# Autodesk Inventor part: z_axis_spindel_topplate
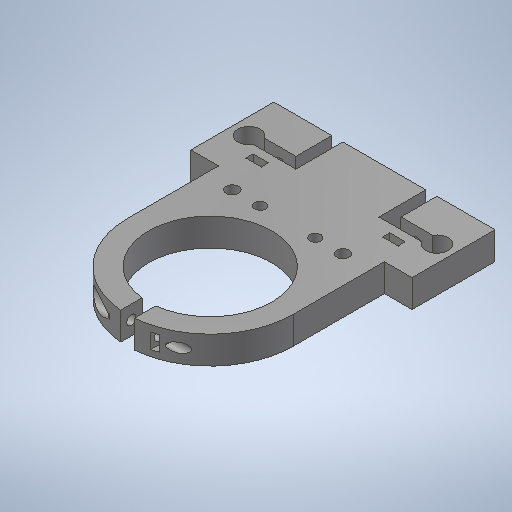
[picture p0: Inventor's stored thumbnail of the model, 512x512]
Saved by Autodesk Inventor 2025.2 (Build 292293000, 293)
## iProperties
Created: 2025-04
Part Number: z_axis_spindel_topplate
Material: 1.0037 S235JR
Document SubType Name: Modeling
Designer: BennF
Density: 7.85 g/cm^3
Appearance: Stahl
Author: BennF
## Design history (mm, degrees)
sketch "Sketch2"
  geometry: L1 (-2.5, -29.896)-(-2.5, -22.159); L2 (2.5, -29.896)-(2.5, -22.159); L3 (-30, 0)-(-30, 33); L4 (-40, 63)-(40, 63); L5 (30, 33)-(30, 0); L6 (-30, 33)-(-40, 33); L7 (-40, 33)-(-40, 63); L8 (30, 33)-(40, 33); L9 (40, 33)-(40, 63); A1 r 22.3 centre (0, 0) between (2.5, -22.159) and (-2.5, -22.159); A2 r 30 centre (0, 0) between (-30, 0) and (-2.5, -29.896); A3 r 30 centre (0, 0) between (2.5, -29.896) and (30, 0); 3 further points
  constraints: 18 end point, 7 point on circle, 4 perpendicular, 3 centre point, 3 coincident, 3 vertical, 2 horizontal, 2 horizontal alignment, 2 parallel, 1 midpoint, 1 tangent, 1 vertical alignment
  dimensions: "d0" = 5 distance between parallel lines of L2 L1; "d1" = 22.3 radius of A1; "d63" = 60 distance between parallel lines of L5 L3; "d64" = 80 distance of L4.start L4.end; "d65" = 30 distance of L8.end L4.end; "d83" = 63 distance from line of point (0, 0) L4
extrude "Extrusion1" new body sketch "Sketch2" distance "d4" = 10; taper "d5" = 0 deg
sketch "Sketch3"
  geometry: L1 (-10, 29.896)-(-10, 0) reference; L2 (-10, 0)-(0, 7.736); L3 (0, 29.896)-(0, 0) reference; L4 (0, 0)-(-10, 7.736); L5 (-10, 7.736)-(0, 7.736) reference; L6 (0, 7.736)-(0, 0) reference; L7 (0, 0)-(-10, 0) reference; L8 (-10, 0)-(-10, 7.736) reference; L9 (-10, 92.896)-(0, 92.896) reference; L10 (0, 92.896)-(0, 52.055) reference; L11 (0, 52.055)-(-10, 52.055) reference; L12 (-10, 52.055)-(-10, 92.896) reference; 2 further points
  constraints: 4 end point, 1 coincident, 1 midpoint
hole "Hole1" sketch "Sketch3" at (-5, 3.868) diameter "d6" = 3.4; stored, may be unused: countersink angle "d10" = 90 deg, drill point angle "d12" = 0 deg; dims "d7" = 3, "d8" = 6.5, "d9" = 3.4, "d11" = 3
sketch "Sketch4"
  geometry: L1 (10, 0)-(0, 0) reference; L2 (0, 0)-(0, 7.736) reference; L3 (0, 7.736)-(10, 7.736) reference; L4 (10, 7.736)-(10, 0) reference; L5 (0, 92.896)-(10, 92.896) reference; L6 (10, 92.896)-(10, 52.055) reference; L7 (10, 52.055)-(0, 52.055) reference; L8 (0, 52.055)-(0, 92.896) reference; L9 (0, 7.736)-(10, 0); L10 (0, 0)-(0, 29.896) reference; L11 (10, 7.736)-(0, 0); 2 further points
  constraints: 4 end point, 1 coincident, 1 midpoint
hole "Hole2" sketch "Sketch4" at (5, 3.868) diameter "d13" = 3.4 (= d6); stored, may be unused: countersink angle "d17" = 90 deg, drill point angle "d19" = 0 deg; dims "d14" = 6, "d15" = 4, "d16" = 2, "d18" = 8
workplane "Work Plane1"
sketch "Sketch5"
  geometry: L1 (5, 7.044)-(7.75, 5.456); L2 (7.75, 5.456)-(7.75, 2.28); L3 (7.75, 2.28)-(5, 0.693); L4 (5, 0.693)-(2.25, 2.28); L5 (2.25, 2.28)-(2.25, 5.456); L6 (2.25, 5.456)-(5, 7.044); L7 (7.75, 2.28)-(7.75, 0.848); L8 (10, 50.897)-(0, 50.897) reference; L9 (10, 8.895)-(10, 0.848) reference; L10 (10, 0.848)-(0, 0.848) reference; L11 (0, 0.848)-(0, 8.895) reference; L12 (0, 92.896)-(10, 92.896) reference; L13 (10, 92.896)-(10, 50.897) reference; L14 (0, 8.895)-(10, 8.895) reference; L15 (0, 50.897)-(0, 92.896) reference; L16 (2.25, 2.28)-(2.25, 0.848); C1 r 1.7 at (5, 3.868) reference; 3 further points
  constraints: 16 end point, 2 point on line, 1 coincident, 1 perpendicular, 1 vertical, 1 vertical alignment, 13 other
  dimensions: "d21" = 5.5 distance between parallel lines of L5 L2
extrude "Extrusion2" cut sketch "Sketch5" distance "d22" = 2.5; taper "d23" = 0 deg
sketch "Sketch6"
  geometry: L1 (10, -23.2)-(50, -23.2); 8 further points; 1 other entity
  constraints: 2 end point, 1 coincident, 1 horizontal, 1 horizontal alignment, 1 midpoint, 1 vertical alignment, 2 other
  dimensions: "d52" = 35 dimension on L1; "d53" = 40 distance of L1.start L1.end
hole "Hole3" sketch "Sketch6" at (10, -23.2), (50, -23.2) diameter "d24" = 4.5; stored, may be unused: countersink angle "d28" = 90 deg, drill point angle "d30" = 118 deg; dims "d25" = 8, "d26" = 10, "d27" = 2, "d29" = 11.8
sketch "Sketch7"
  geometry: L1 (40, -23.2)-(20, -23.2); C1 r 2.25 at (50, -23.2) reference; 7 further points; 1 other entity
  constraints: 2 end point, 2 horizontal alignment, 1 horizontal, 1 midpoint, 1 vertical alignment, 2 other
  dimensions: "d40" = 20 distance of L1.start L1.end
hole "Hole4" sketch "Sketch7" at (40, -23.2), (20, -23.2) diameter "d33" = 4; stored, may be unused: countersink angle "d37" = 90 deg, drill point angle "d39" = 0 deg; dims "d34" = 10, "d35" = 6.5, "d36" = 3.4, "d38" = 25
sketch "Sketch10"
  geometry: L1 (-34, 48)-(34, 48); L2 (40, 63)-(-40, 63) reference; 2 further points
  constraints: 2 end point, 1 horizontal, 1 horizontal alignment, 1 midpoint, 1 vertical alignment
  dimensions: "d61" = 68 distance of L1.start L1.end; "d62" = 15 distance between parallel lines of L2 L1
hole "Hole5" sketch "Sketch10" at (-34, 48), (34, 48) diameter "d54" = 8.15; stored, may be unused: countersink angle "d58" = 90 deg, drill point angle "d60" = 118 deg; dims "d55" = 6, "d56" = 6.3, "d57" = 2, "d59" = 8
workpoint "Work Point1"
workplane "Work Plane2"
  workaxis "Work Axis2"
sketch "Sketch11"
  geometry: L1 (27.5, -5)-(27.5, -2.05); L2 (27.5, -2.05)-(5, -2.05); L3 (5, -2.05)-(5, -5); L4 (27.5, -5)-(5, -5); L5 (0, -6.7)-(0, -3.3) reference; L6 (27.5, -10)-(27.5, 0) reference; 3 further points
  constraints: 8 end point, 3 point on line, 2 perpendicular, 1 horizontal, 1 vertical, 1 other
  dimensions: "d66" = 5.9 diameter of L2 L4; "d67" = 5 distance between parallel lines of L5 L3
revolve "Revolution1" sketch "Sketch11" stored, may be unused: angle "d68" = 90 deg
sketch "Sketch12"
  geometry: L1 (40, 63)-(-40, 63) reference; L2 (-30.45, 50)-(-19, 50); L3 (-19, 50)-(-19, 63); L4 (-15, 63)-(-15, 46); L5 (-15, 46)-(-30.45, 46); L6 (19, 63)-(19, 50); L7 (19, 50)-(30.45, 50); L8 (15, 63)-(15, 46); L9 (15, 46)-(30.45, 46); L10 (-19, 50)-(-15, 50); L11 (-19, 50)-(-19, 46); L12 (27.525, 40.4)-(21.925, 40.4); L13 (21.925, 40.4)-(21.925, 43); L14 (21.925, 43)-(27.525, 43); L15 (27.525, 43)-(27.525, 40.4); L16 (-21.925, 40.4)-(-27.525, 40.4); L17 (-27.525, 40.4)-(-27.525, 43); L18 (-27.525, 43)-(-21.925, 43); L19 (-21.925, 43)-(-21.925, 40.4); A1 r 4.075 centre (-34, 48) between (-30.45, 50) and (-30.45, 46) reference; A2 r 4.075 centre (34, 48) between (30.45, 50) and (30.45, 46) reference; 6 further points
  constraints: 36 end point, 8 perpendicular, 8 point on line, 5 midpoint, 4 equal length, 4 parallel, 4 point on circle, 4 vertical alignment, 3 horizontal, 3 vertical, 1 horizontal alignment
  dimensions: "d69" = 4 distance between parallel lines of L5 L2; "d70" = 15 distance from line of L3 A1.centre; "d71" = 3 distance from line of point (22.725, 46) L14; "d72" = 5.6 distance of L16.start L16.end; "d73" = 2.6 distance of L16.end L17.end
extrude "Extrusion4" cut sketch "Sketch12" distance "d74" = 10; taper "d75" = 0 deg
sketch "Sketch13"
  geometry: L1 (-21, 10)-(-21, 0) reference; L2 (-59, 0)-(-59, 10) reference; L3 (-18.075, 0)-(-12.475, 0) reference; L4 (-67.525, 0)-(-61.925, 0) reference; 7 further points
  constraints: 4 midpoint, 2 horizontal alignment, 2 vertical alignment
hole "Hole6" sketch "Sketch13" at (-15.275, 5), (-64.725, 5) diameter "d76" = 3.4; stored, may be unused: countersink angle "d80" = 90 deg, drill point angle "d82" = 0 deg; dims "d77" = 6, "d78" = 7.5, "d79" = 2, "d81" = 23
body "Solid1"
node "Project Cut Edges1"
node "Project Cut Edges2"
node "Project Cut Edges3"
other parameters: "d3" = 37.8, "d20" = -5, "d42" = 8.75
